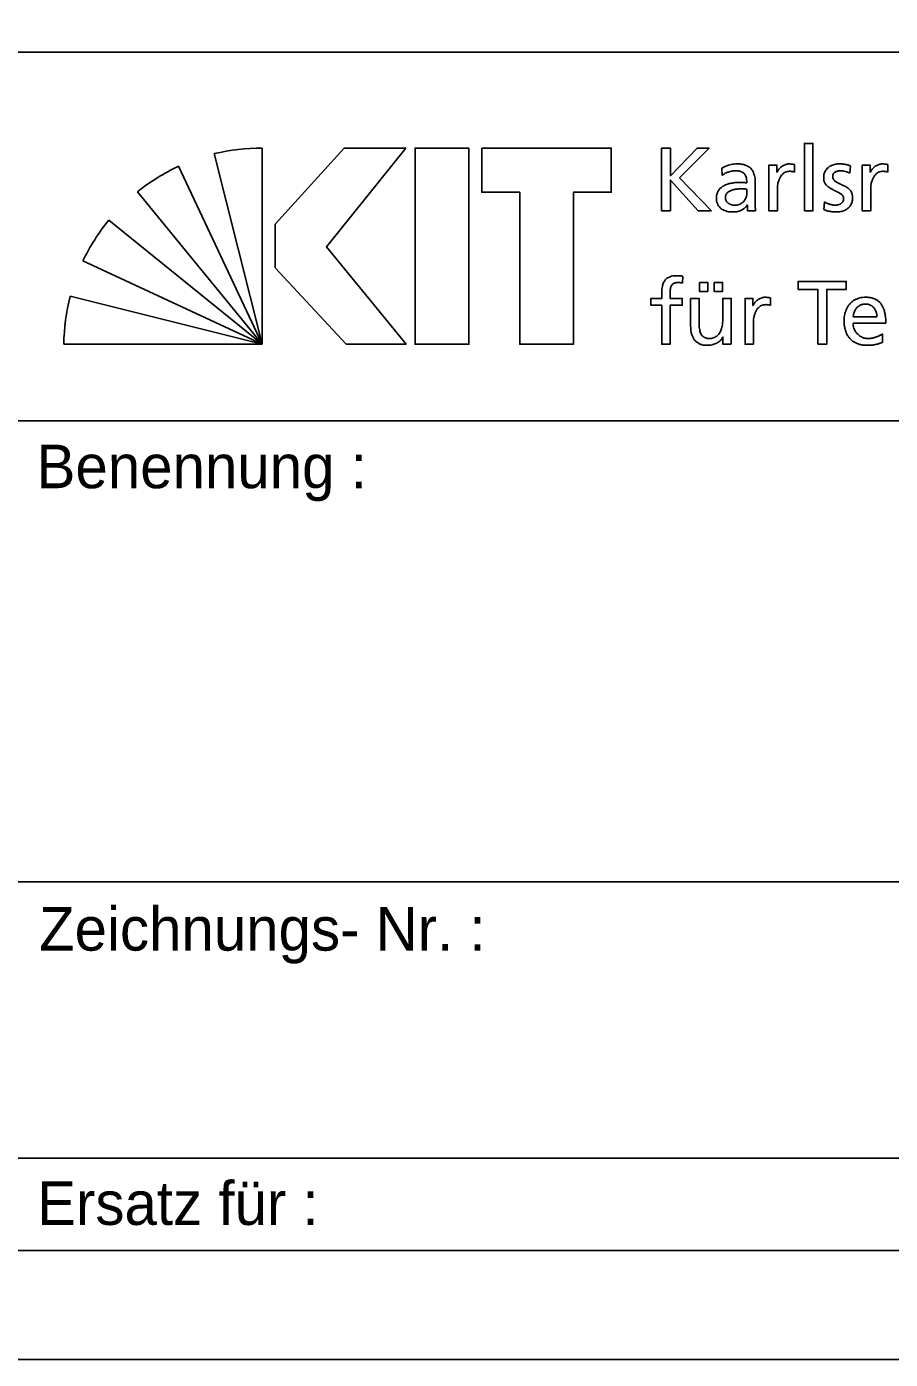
# Model space of a CAD drawing. Extents: x 0 to 59.4, y 0 to 42.
# Drawn here: x 50.57 to 54.53, y 0 to 6.12 of the extents above; entities that cross this region are included whole.
import ezdxf

# ---------------------------------------------------------------- set-up
doc = ezdxf.new("R2010")
doc.units = 0
doc.layers.add('90_Plankopf', color=7, linetype='Continuous')

msp = doc.modelspace()

# ---------------------------------------------------------------- linework, layer by layer
at = {"layer": '90_Plankopf'}
for p, q in [((41.112, 5.999), (58.9, 5.999)), ((41.112, 5.999), (58.9, 5.999)), ((51.4275, 5.5333), (51.6481, 4.6586)), ((51.6481, 4.6586), (51.6481, 5.5584)), ((53.481, 5.5586), (53.481, 5.2706)), ((51.6481, 4.6586), (51.2633, 5.4752)), ((53.7579, 5.4662), (53.76, 5.4332)), ((54.0926, 5.4484), (54.0926, 5.4831)), ((54.3457, 5.4439), (54.349, 5.4778)), ((54.5211, 5.4484), (54.5211, 5.4831)), ((53.9118, 5.3118), (53.9118, 5.3989)), ((51.0744, 5.3585), (51.6481, 4.6586)), ((53.873, 5.3709), (53.873, 5.3523)), ((53.481, 5.2706), (53.5222, 5.2706)), ((53.6506, 5.2706), (53.7108, 5.2706)), ((54.2297, 5.3118), (54.2277, 5.2772)), ((51.6481, 4.6586), (50.9434, 5.2286)), ((50.824, 5.0413), (51.6481, 4.6586)), ((53.5773, 4.9393), (53.579, 4.9706)), ((51.6481, 4.6586), (50.7658, 4.8788)), ((53.9827, 4.8365), (53.9827, 4.8712)), ((54.4706, 4.7841), (54.3616, 4.7841)), ((54.3616, 4.7552), (54.5119, 4.7552)), ((50.7364, 4.6586), (51.6481, 4.6586)), ((54.4958, 4.6673), (54.4958, 4.7061)), ((50.5001, 4.307), (58.9, 4.307)), ((50.5001, 2.192), (58.9, 2.192)), ((50.5001, 0.923), (58.9, 0.923)), ((58.9, 0.5), (41.112, 0.5)), ((42.28, 0.5), (58.9, 0.5)), ((42.28, 0.5), (58.9, 0.5))]:
    msp.add_line(p, q, dxfattribs=at)
for points in [[(0, 0), (59.4, 0), (59.4, 42), (0, 42)], [(2.5, 41.5), (58.9, 41.5), (58.9, 0.5), (2.5, 0.5)], [(52.3066, 5.5586), (52.0236, 5.5586), (51.7073, 5.2099), (51.7073, 5.0092), (52.0338, 4.6586), (52.3085, 4.6586), (51.9422, 5.1063)], [(52.597, 5.5586), (52.597, 4.6586), (52.3501, 4.6586), (52.3501, 5.5586)], [(52.6562, 5.5586), (52.6562, 5.356), (52.8301, 5.356), (52.8301, 4.6586), (53.0771, 4.6586), (53.0771, 5.356), (53.251, 5.356), (53.251, 5.5586)]]:
    msp.add_lwpolyline(points, close=True, dxfattribs=at)
for points in [[(54.1381, 5.2706), (54.1768, 5.2706), (54.1768, 5.5801), (54.1381, 5.5801), (54.1381, 5.2706)], [(53.7108, 5.2706), (53.5647, 5.4224), (53.7001, 5.5586), (53.6452, 5.5586), (53.5222, 5.4319), (53.5222, 5.5586), (53.481, 5.5586)], [(54.0122, 5.4484), (54.0113, 5.4484), (54.0113, 5.481), (53.975, 5.481), (53.975, 5.2706), (54.0138, 5.2706), (54.0138, 5.3663)], [(54.4407, 5.4484), (54.4398, 5.4484), (54.4398, 5.481), (54.4035, 5.481), (54.4035, 5.2706), (54.4423, 5.2706), (54.4423, 5.3663)], [(53.5222, 5.2706), (53.5222, 5.4117), (53.6506, 5.2706)], [(53.8763, 5.2978), (53.8772, 5.2978), (53.8772, 5.2706), (53.9135, 5.2706)], [(53.6554, 4.9426), (53.6554, 4.9013), (53.6942, 4.9013), (53.6942, 4.9426), (53.6554, 4.9426)], [(53.7231, 4.9426), (53.7231, 4.9013), (53.7619, 4.9013), (53.7619, 4.9426), (53.7231, 4.9426)], [(54.199, 4.6586), (54.2403, 4.6586), (54.2403, 4.9104), (54.3298, 4.9104), (54.3298, 4.9467), (54.1094, 4.9467), (54.1094, 4.9104), (54.199, 4.9104), (54.199, 4.6586)], [(53.4824, 4.8885), (53.4824, 4.8691), (53.4329, 4.8691), (53.4329, 4.8378), (53.4824, 4.8378), (53.4824, 4.6586), (53.5212, 4.6586), (53.5212, 4.8378), (53.5769, 4.8378), (53.5769, 4.8691), (53.5212, 4.8691), (53.5212, 4.8918)], [(53.6542, 4.7602), (53.6542, 4.8691), (53.6154, 4.8691), (53.6154, 4.7441)], [(53.8015, 4.6586), (53.8015, 4.8691), (53.7627, 4.8691), (53.7627, 4.7717)], [(53.9022, 4.8365), (53.9014, 4.8365), (53.9014, 4.8691), (53.8651, 4.8691), (53.8651, 4.6586), (53.9039, 4.6586), (53.9039, 4.7544)], [(53.7631, 4.6921), (53.7639, 4.6921), (53.7639, 4.6586), (53.8015, 4.6586)]]:
    msp.add_lwpolyline(points, dxfattribs=at)
for centre, start, end in [((51.6449, 4.6056), 89.80527, 103.18947), ((51.6662, 4.6118), 115.01261, 128.3968), ((51.6816, 4.6263), 140.78977, 154.17397), ((51.6891, 4.6438), 165.72225, 179.10644)]:
    msp.add_arc(centre, 0.9528, start, end, dxfattribs=at)
for points in [[(53.9118, 5.3989), (53.9119, 5.418), (53.9091, 5.4341), (53.9033, 5.447), (53.8975, 5.4599), (53.8884, 5.4696), (53.8759, 5.4762), (53.8635, 5.4827), (53.8472, 5.486), (53.8272, 5.486), (53.8138, 5.4859), (53.8014, 5.4841), (53.7898, 5.4804), (53.7782, 5.4768), (53.7676, 5.4721), (53.7579, 5.4662)], [(53.76, 5.4332), (53.7653, 5.4376), (53.7713, 5.4414), (53.7779, 5.4446), (53.7846, 5.4478), (53.7916, 5.4503), (53.799, 5.452), (53.8063, 5.4538), (53.8137, 5.4546), (53.821, 5.4546), (53.8339, 5.4546), (53.8441, 5.4526), (53.8518, 5.4485), (53.8594, 5.4444), (53.8649, 5.4383), (53.8682, 5.4302), (53.8715, 5.4219), (53.8731, 5.4118), (53.873, 5.3997)], [(54.0926, 5.4831), (54.0899, 5.4837), (54.0873, 5.4841), (54.0849, 5.4846), (54.0824, 5.485), (54.0798, 5.4854), (54.0769, 5.4856), (54.0741, 5.4859), (54.0708, 5.486), (54.067, 5.486), (54.0595, 5.4859), (54.0523, 5.4843), (54.0452, 5.4811), (54.0382, 5.4779), (54.0318, 5.4736), (54.0261, 5.4679), (54.0203, 5.4623), (54.0157, 5.4558), (54.0122, 5.4484)], [(54.0138, 5.3663), (54.0139, 5.384), (54.0163, 5.3993), (54.021, 5.4121), (54.0257, 5.4249), (54.0323, 5.4348), (54.0409, 5.4416), (54.0494, 5.4486), (54.0595, 5.4521), (54.0712, 5.4521), (54.0746, 5.4522), (54.078, 5.4519), (54.0818, 5.4514), (54.0855, 5.4509), (54.0891, 5.4499), (54.0926, 5.4484)], [(54.349, 5.4778), (54.3414, 5.4801), (54.3337, 5.482), (54.3259, 5.4836), (54.3181, 5.4851), (54.3097, 5.4859), (54.3007, 5.486), (54.2903, 5.486), (54.2805, 5.4847), (54.2716, 5.482), (54.2625, 5.4794), (54.2547, 5.4753), (54.248, 5.47), (54.2412, 5.4647), (54.2359, 5.4579), (54.2322, 5.4498), (54.2284, 5.4417), (54.2265, 5.4321), (54.2264, 5.4212), (54.2265, 5.4128), (54.2282, 5.4056), (54.2315, 5.3994), (54.2347, 5.3933), (54.2391, 5.388), (54.2445, 5.3834), (54.25, 5.379), (54.2559, 5.375), (54.2623, 5.3715), (54.2688, 5.368), (54.2753, 5.3647), (54.2817, 5.3617), (54.2882, 5.3586), (54.2942, 5.3555), (54.2995, 5.3522), (54.305, 5.349), (54.3093, 5.3454), (54.3126, 5.3413), (54.3158, 5.3373), (54.3176, 5.3325), (54.3176, 5.3271), (54.3176, 5.3215), (54.3163, 5.3167), (54.3139, 5.3128), (54.3116, 5.309), (54.3084, 5.3059), (54.3045, 5.3035), (54.3006, 5.3012), (54.2963, 5.2995), (54.2917, 5.2985), (54.2871, 5.2975), (54.2825, 5.297), (54.278, 5.297), (54.2742, 5.297), (54.2695, 5.2975), (54.2639, 5.2986), (54.2584, 5.2997), (54.2526, 5.3014), (54.2466, 5.3036), (54.2405, 5.3058), (54.235, 5.3085), (54.2297, 5.3118)], [(54.2277, 5.2772), (54.2366, 5.2726), (54.246, 5.2694), (54.2558, 5.2678), (54.2656, 5.2662), (54.2755, 5.2655), (54.2854, 5.2656), (54.2949, 5.2656), (54.304, 5.2669), (54.3127, 5.2695), (54.3215, 5.2722), (54.3293, 5.2762), (54.3363, 5.2816), (54.3431, 5.2869), (54.3487, 5.2938), (54.3527, 5.302), (54.3568, 5.3103), (54.3588, 5.32), (54.3589, 5.3312), (54.3588, 5.3408), (54.3571, 5.3489), (54.3539, 5.3556), (54.3506, 5.3622), (54.3462, 5.3679), (54.3408, 5.3726), (54.3354, 5.3772), (54.3295, 5.3811), (54.323, 5.3845), (54.3165, 5.3878), (54.3101, 5.3909), (54.3036, 5.3937), (54.2971, 5.3966), (54.2912, 5.3995), (54.2858, 5.4026), (54.2804, 5.4058), (54.276, 5.4095), (54.2727, 5.4136), (54.2695, 5.4179), (54.2678, 5.423), (54.2677, 5.4291), (54.2678, 5.4348), (54.2696, 5.4396), (54.2729, 5.4434), (54.2763, 5.4472), (54.2808, 5.45), (54.2864, 5.4519), (54.292, 5.4538), (54.2982, 5.4546), (54.3048, 5.4546), (54.3072, 5.4546), (54.3102, 5.4543), (54.3139, 5.4538), (54.3175, 5.4531), (54.3213, 5.4523), (54.3254, 5.4513), (54.3295, 5.4503), (54.3333, 5.4491), (54.3369, 5.4478), (54.3405, 5.4466), (54.3434, 5.4453), (54.3457, 5.4439)], [(54.5211, 5.4831), (54.5184, 5.4837), (54.5158, 5.4841), (54.5134, 5.4846), (54.511, 5.485), (54.5083, 5.4854), (54.5054, 5.4856), (54.5026, 5.4859), (54.4993, 5.486), (54.4955, 5.486), (54.488, 5.4859), (54.4808, 5.4843), (54.4737, 5.4811), (54.4667, 5.4779), (54.4603, 5.4736), (54.4546, 5.4679), (54.4488, 5.4623), (54.4442, 5.4558), (54.4407, 5.4484)], [(54.4423, 5.3663), (54.4424, 5.384), (54.4448, 5.3993), (54.4495, 5.4121), (54.4542, 5.4249), (54.4608, 5.4348), (54.4694, 5.4416), (54.4779, 5.4486), (54.488, 5.4521), (54.4997, 5.4521), (54.503, 5.4522), (54.5065, 5.4519), (54.5103, 5.4514), (54.514, 5.4509), (54.5175, 5.4499), (54.5211, 5.4484)], [(53.873, 5.3997), (53.868, 5.4), (53.8633, 5.4002), (53.8589, 5.4003), (53.8546, 5.4004), (53.8502, 5.4005), (53.8459, 5.4006), (53.8415, 5.4006), (53.8368, 5.4006), (53.8318, 5.4006), (53.8237, 5.4006), (53.8151, 5.3999), (53.8063, 5.3984), (53.7973, 5.397), (53.7886, 5.3947), (53.7801, 5.3914), (53.7715, 5.3881), (53.7638, 5.3838), (53.7569, 5.3785), (53.7499, 5.3731), (53.7444, 5.3665), (53.7403, 5.3588), (53.7362, 5.3509), (53.7341, 5.3418), (53.734, 5.3312), (53.7341, 5.316), (53.7374, 5.3035), (53.7439, 5.2939), (53.7504, 5.2842), (53.7594, 5.277), (53.771, 5.2724), (53.7825, 5.2679), (53.7959, 5.2656), (53.8111, 5.2656), (53.82, 5.2657), (53.828, 5.2668), (53.835, 5.2689), (53.8421, 5.2709), (53.8483, 5.2736), (53.8536, 5.2769), (53.859, 5.2802), (53.8635, 5.2837), (53.8673, 5.2874), (53.871, 5.2911), (53.8741, 5.2945), (53.8763, 5.2978)], [(53.873, 5.3523), (53.873, 5.3418), (53.8708, 5.3323), (53.8664, 5.324), (53.862, 5.3157), (53.8554, 5.3092), (53.8467, 5.3043), (53.838, 5.2995), (53.8272, 5.297), (53.8144, 5.297), (53.81, 5.297), (53.8054, 5.2978), (53.8008, 5.2992), (53.7963, 5.3007), (53.792, 5.3028), (53.7882, 5.3057), (53.7843, 5.3087), (53.7812, 5.3123), (53.7789, 5.3165), (53.7765, 5.3207), (53.7753, 5.3257), (53.7752, 5.3312), (53.7754, 5.3386), (53.7772, 5.3448), (53.7808, 5.3497), (53.7844, 5.3546), (53.7891, 5.3586), (53.7949, 5.3615), (53.8007, 5.3645), (53.8069, 5.3667), (53.8135, 5.3682), (53.8201, 5.3696), (53.8265, 5.3706), (53.8326, 5.3711), (53.8387, 5.3715), (53.8439, 5.3717), (53.8483, 5.3717), (53.8524, 5.3717), (53.8565, 5.3715), (53.8607, 5.3713), (53.8648, 5.3711), (53.8689, 5.3709), (53.873, 5.3709)], [(53.9135, 5.2706), (53.9132, 5.2726), (53.9129, 5.2753), (53.9126, 5.2787), (53.9125, 5.2821), (53.9122, 5.2865), (53.9121, 5.2919), (53.9119, 5.2973), (53.9118, 5.3039), (53.9118, 5.3118)], [(53.579, 4.9706), (53.5751, 4.9712), (53.571, 4.9719), (53.5668, 4.9723), (53.5625, 4.9728), (53.5579, 4.9731), (53.553, 4.9731), (53.5388, 4.973), (53.527, 4.971), (53.5178, 4.9671), (53.5086, 4.9631), (53.5014, 4.9574), (53.4962, 4.95), (53.491, 4.9426), (53.4875, 4.9337), (53.4854, 4.9233), (53.4833, 4.9129), (53.4824, 4.9014), (53.4824, 4.8885)], [(53.5212, 4.8918), (53.5212, 4.899), (53.5216, 4.9056), (53.5224, 4.9116), (53.5232, 4.9177), (53.5249, 4.923), (53.5275, 4.9275), (53.53, 4.932), (53.5338, 4.9355), (53.5388, 4.9379), (53.5439, 4.9404), (53.5505, 4.9417), (53.5588, 4.9417), (53.5621, 4.9417), (53.5655, 4.9415), (53.5688, 4.9411), (53.5722, 4.9407), (53.575, 4.9401), (53.5773, 4.9393)], [(53.9827, 4.8712), (53.98, 4.8717), (53.9774, 4.8722), (53.975, 4.8727), (53.9725, 4.8731), (53.9698, 4.8734), (53.967, 4.8737), (53.9642, 4.8739), (53.9609, 4.874), (53.9571, 4.874), (53.9496, 4.874), (53.9423, 4.8724), (53.9352, 4.8692), (53.9282, 4.866), (53.9218, 4.8616), (53.9161, 4.856), (53.9104, 4.8503), (53.9057, 4.8439), (53.9022, 4.8365)], [(53.9039, 4.7544), (53.9039, 4.7721), (53.9064, 4.7873), (53.911, 4.8001), (53.9158, 4.8129), (53.9224, 4.8228), (53.931, 4.8297), (53.9395, 4.8367), (53.9496, 4.8401), (53.9612, 4.8402), (53.9646, 4.8403), (53.9681, 4.84), (53.9718, 4.8395), (53.9756, 4.8389), (53.9791, 4.8379), (53.9827, 4.8365)], [(54.5119, 4.7552), (54.5119, 4.7722), (54.5103, 4.788), (54.5072, 4.8023), (54.5041, 4.8168), (54.4989, 4.8293), (54.4918, 4.84), (54.4846, 4.8507), (54.4751, 4.8591), (54.4631, 4.865), (54.4512, 4.8709), (54.4365, 4.874), (54.419, 4.874), (54.4041, 4.874), (54.3906, 4.8714), (54.3785, 4.8662), (54.3665, 4.861), (54.3561, 4.8537), (54.3474, 4.8442), (54.3387, 4.8347), (54.3321, 4.8235), (54.3275, 4.8105), (54.3228, 4.7976), (54.3205, 4.7833), (54.3204, 4.7676), (54.3204, 4.7504), (54.3225, 4.7348), (54.3269, 4.7209), (54.3312, 4.7069), (54.3379, 4.695), (54.3469, 4.685), (54.3558, 4.6749), (54.3671, 4.6672), (54.3808, 4.6619), (54.3945, 4.6564), (54.4107, 4.6538), (54.4293, 4.6537), (54.4408, 4.6538), (54.4506, 4.6545), (54.4587, 4.656), (54.4667, 4.6575), (54.4737, 4.6593), (54.4797, 4.6614), (54.4855, 4.6634), (54.4909, 4.6654), (54.4958, 4.6673)], [(54.3616, 4.7841), (54.3623, 4.791), (54.3639, 4.7978), (54.3664, 4.8047), (54.3688, 4.8116), (54.3722, 4.8179), (54.3768, 4.8236), (54.3812, 4.8294), (54.3869, 4.8339), (54.3937, 4.8374), (54.4006, 4.8408), (54.4087, 4.8426), (54.4182, 4.8427), (54.4266, 4.8426), (54.434, 4.8411), (54.4404, 4.8381), (54.447, 4.835), (54.4524, 4.8309), (54.4569, 4.8255), (54.4614, 4.8201), (54.4648, 4.8139), (54.4671, 4.8069), (54.4694, 4.7998), (54.4706, 4.7922), (54.4706, 4.7841)], [(53.7627, 4.7717), (53.7627, 4.7589), (53.7615, 4.7471), (53.7589, 4.7365), (53.7564, 4.726), (53.7525, 4.7169), (53.7473, 4.7092), (53.7421, 4.7015), (53.7354, 4.6956), (53.7273, 4.6914), (53.7193, 4.6872), (53.7097, 4.6851), (53.6987, 4.685), (53.6875, 4.6857), (53.6786, 4.6889), (53.6721, 4.6945), (53.6656, 4.7002), (53.661, 4.7084), (53.6582, 4.7193), (53.6554, 4.7302), (53.6541, 4.7438), (53.6542, 4.7602)], [(53.6154, 4.7441), (53.6154, 4.7251), (53.6181, 4.709), (53.6237, 4.6955), (53.6293, 4.682), (53.6379, 4.6717), (53.6496, 4.6645), (53.6612, 4.6574), (53.6761, 4.6538), (53.6942, 4.6537), (53.704, 4.6538), (53.7135, 4.6553), (53.7225, 4.6583), (53.7315, 4.6614), (53.7396, 4.6658), (53.7466, 4.6715), (53.7537, 4.6772), (53.7592, 4.6841), (53.7631, 4.6921)], [(54.4958, 4.7061), (54.4933, 4.7041), (54.4899, 4.7019), (54.4852, 4.6995), (54.4806, 4.6971), (54.4754, 4.6948), (54.4694, 4.6926), (54.4634, 4.6904), (54.4572, 4.6886), (54.4506, 4.6872), (54.444, 4.6858), (54.4374, 4.6851), (54.4309, 4.685), (54.4217, 4.6851), (54.413, 4.6868), (54.4046, 4.6902), (54.3964, 4.6935), (54.3889, 4.6983), (54.3825, 4.7045), (54.3761, 4.7107), (54.371, 4.7181), (54.3673, 4.7267), (54.3636, 4.7353), (54.3617, 4.7448), (54.3616, 4.7552)]]:
    msp.add_open_spline(points, degree=3, dxfattribs=at)

# ---------------------------------------------------------------- texts
for s, p in [('Benennung :', (50.6113, 3.9979)), ('Zeichnungs- Nr. :', (50.6227, 1.8758)), ('Ersatz für :', (50.6139, 0.6169))]:
    msp.add_text(s, height=0.2, dxfattribs=at).set_placement(p)

doc.saveas('drawing.dxf')
